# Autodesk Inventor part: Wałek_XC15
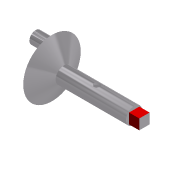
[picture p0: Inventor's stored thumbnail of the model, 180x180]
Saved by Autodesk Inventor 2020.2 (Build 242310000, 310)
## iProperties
Created: 2000-05
Part Number: Wałek_XC15
Document SubType Name: Modeling
Designer: F.Stasiak
Stock Number: Wałek_XC15
Density: 7.85 g/cm^3
Material: Stal kuta
Appearance: Aluminium (polerowane)
Mass: 2925.95 g
Surface Area: 719.441 cm^2
Volume: 372.733 cm^3
Catalog Web Link: www.expertbooks.pl
Manager: www.cadconsulting.pl
Company: Fabian Stasiak CAD Consulting
Control State: 0
Master: False
Checked Out: False
Shininess: 0.0
Density: 0.0
Volumn: 0.0
Area: 0.0
PropertySet Name: Model Information
Author: F.Stasiak
Subject: Zbiór ćwiczeń. Autodesk Inventor 2020. Kurs Professional
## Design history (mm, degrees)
node "Base1"
node "Bryła1"
node "Korpusy bryłowe"
node "Korpusy powierzchniowe"
